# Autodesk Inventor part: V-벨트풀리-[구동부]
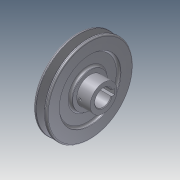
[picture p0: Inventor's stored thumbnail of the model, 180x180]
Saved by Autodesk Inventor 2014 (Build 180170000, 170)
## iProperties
Company: 한국ATC센터
Created: 2014-10
Part Number: V-벨트풀리-[구동부]
Document SubType Name: Modeling
Designer: 한국ATC센터
Density: 7.86 g/cm^3
Material: 강, 연강
Mass: 1515.01 g
Surface Area: 468.111 cm^2
Volume: 192.75 cm^3
Appearance: 강철
Author: KYOUNG IL JANG
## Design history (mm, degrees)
sketch "스케치1"
  geometry: L1 (-20, 0)-(20, 0); L2 (-20, 0)-(-20, 26); L3 (-20, 26)-(-16, 26); L4 (-16, 26)-(-16, 46); L5 (-16, 46)-(-20, 46); L6 (-20, 46)-(-20, 64.5); L7 (-20, 64.5)-(-16.062, 64.5); L8 (-16.062, 64.5)-(-12.001, 52); L9 (-12.001, 52)-(-7.999, 52); L10 (-7.999, 52)-(-3.938, 64.5); L11 (-3.938, 64.5)-(0, 64.5); L12 (0, 64.5)-(0, 46); L13 (0, 46)-(-4, 46); L14 (-4, 46)-(-4, 26); L15 (-4, 26)-(0, 26); L16 (0, 26)-(0, 20); L17 (0, 20)-(20, 20); L18 (20, 20)-(20, 0); L19 (-14.6, 60)-(-5.4, 60); 2 further points
  constraints: 38 end point, 11 parallel, 7 collinear, 3 equal length, 3 perpendicular, 2 point on line, 1 coincident, 1 horizontal, 1 midpoint
  dimensions: "d0" = 40 distance of L1.start L1.end; "d1" = 4.5 distance between parallel lines of L7 L19; "d2" = 8 distance between parallel lines of L9 L19; "d3" = 9.2 distance of L19.start L19.end; "d4" = 36 deg angle of L10 L8; "d5" = 20 distance between parallel lines of L12 L6; "d6" = 120 diameter of L19 L1; "d7" = 4 distance of L2.end L3.end; "d8" = 52 diameter of L3 L1; "d9" = 92 diameter of L5 L1; "d10" = 40 diameter of L17 L1
revolve "회전1" sketch "스케치1" stored, may be unused: angle "d11" = 90 deg
sketch "스케치2"
  geometry: L1 (-4, 11.843)-(-4, 16.5); L2 (-4, 16.5)-(4, 16.5); L3 (4, 16.5)-(4, 11.843); A1 r 12.5 centre (0, 0) between (-4, 11.843) and (4, 11.843); 1 further point
  constraints: 6 end point, 2 parallel, 2 point on circle, 1 centre point, 1 coincident, 1 horizontal, 1 vertical
  dimensions: "d12" = 25 diameter of A1; "d13" = 8 distance of L1.end L2.end; "d14" = 29 dimension on A1 L2
extrude "돌출1" cut sketch "스케치2" stored distance "d15" = 10; taper "d16" = 0 deg
chamfer "모따기1" distance "d17" = 1; stored, may be unused: second distance "d18" = 2, angle "d19" = 45 deg
node "작업 평면1"
sketch "스케치3"
  geometry: L1 (10, -20)-(10, 20) reference; 3 further points
  constraints: 1 horizontal alignment, 1 midpoint
  dimensions: "d20" = 15 distance from line of L1 point (-5, 0)
hole "구멍1" sketch "스케치3" at (-5, 0) diameter "d21" = 4.459; stored, may be unused: countersink angle "d25" = 90 deg, drill point angle "d27" = 118 deg; dims "d22" = 6, "d23" = 4, "d24" = 2, "d26" = 8
fillet "모깎기1" dims "d28" = 3, "d29" = 2, "d30" = 0.5, "d31" = 1
node "솔리드1"
